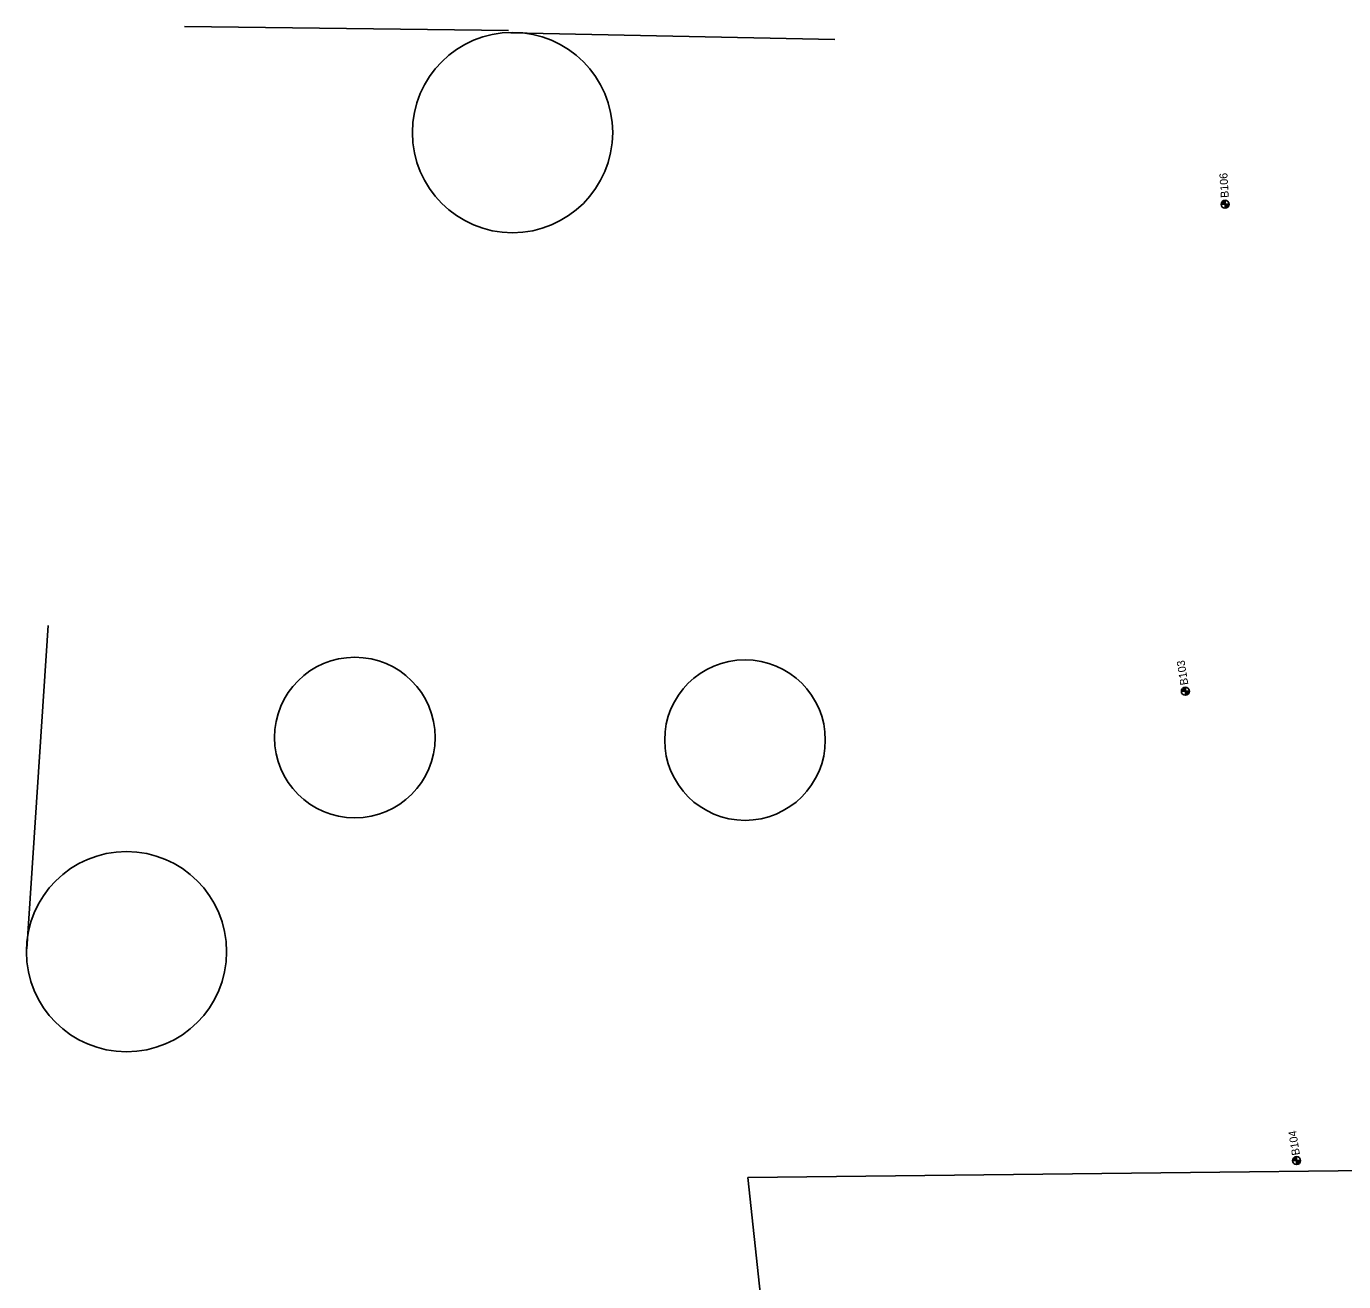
# Model space of a CAD drawing. Extents: x 311409 to 379449, y 121539 to 224848.
# Drawn here: x 354135 to 355782, y 184658 to 186227 of the extents above; entities that cross this region are included whole.
import ezdxf

# ---------------------------------------------------------------- set-up
doc = ezdxf.new("R2010")
doc.units = 0
for name, color, linetype in [('CE-TOPO-CONC-SLAB', 7, 'Continuous'), ('E_SOIL_BORE1 [KAPUR_CADDS_LEVELS]', 7, 'Continuous'), ('E_SOIL_BORE2 [KAPUR_CADDS_LEVELS]', 7, 'Continuous'), ('P_MARK', 7, 'Continuous'), ('P_TC', 7, 'Continuous'), ('SIGNS-POLES', 7, 'Continuous')]:
    doc.layers.add(name, color=color, linetype=linetype)

msp = doc.modelspace()

# ---------------------------------------------------------------- linework, layer by layer
at = {"layer": 'CE-TOPO-CONC-SLAB'}
for centre in [(354545.6, 185338.2), (355033.3, 185335.1)]:
    msp.add_circle(centre, 100.4, dxfattribs=at)
at = {"layer": 'P_MARK'}
for p, q in [((355628.3, 186004.9), (355638.3, 186004.9)), ((355633.3, 186009.9), (355633.3, 185999.9)), ((355578.7, 185396.1), (355588.7, 185396.1)), ((355583.7, 185401.1), (355583.7, 185391.1)), ((355722.7, 184814.3), (355722.7, 184804.3)), ((355717.7, 184809.3), (355727.7, 184809.3))]:
    msp.add_line(p, q, dxfattribs=at)
for centre in [(355633.3, 186004.9), (355583.7, 185396.1), (355722.7, 184809.3)]:
    msp.add_circle(centre, 5, dxfattribs=at)
for centre, radius, start, end in [((355633.3, 186004.9), 4.5, 89.9869, 179.9869), ((355633.3, 186004.9), 4, 89.9869, 179.9869), ((355633.3, 186004.9), 3.5, 89.9869, 179.9869), ((355633.3, 186004.9), 3, 89.9869, 179.9869), ((355633.3, 186004.9), 2.5, 89.9869, 179.9869), ((355633.3, 186004.9), 2, 89.9869, 179.9869), ((355633.3, 186004.9), 1.5, 89.9869, 179.9869), ((355633.3, 186004.9), 1, 89.9869, 179.9869), ((355633.3, 186004.9), 0.5, 89.9869, 179.9869), ((355633.3, 186004.9), 4.5, 269.9869, 359.9869), ((355633.3, 186004.9), 4, 269.9869, 359.9869), ((355633.3, 186004.9), 3.5, 269.9869, 359.9869), ((355633.3, 186004.9), 3, 269.9869, 359.9869), ((355633.3, 186004.9), 2.5, 269.9869, 359.9869), ((355633.3, 186004.9), 2, 269.9869, 359.9869), ((355633.3, 186004.9), 1.5, 269.9869, 359.9869), ((355633.3, 186004.9), 1, 269.9869, 359.9869), ((355633.3, 186004.9), 0.5, 269.9869, 359.9869), ((355583.7, 185396.1), 4.5, 89.9869, 179.9869), ((355583.7, 185396.1), 4, 89.9869, 179.9869), ((355583.7, 185396.1), 3.5, 89.9869, 179.9869), ((355583.7, 185396.1), 3, 89.9869, 179.9869), ((355583.7, 185396.1), 2.5, 89.9869, 179.9869), ((355583.7, 185396.1), 2, 89.9869, 179.9869), ((355583.7, 185396.1), 1.5, 89.9869, 179.9869), ((355583.7, 185396.1), 1, 89.9869, 179.9869), ((355583.7, 185396.1), 0.5, 89.9869, 179.9869), ((355583.7, 185396.1), 4.5, 269.9869, 359.9869), ((355583.7, 185396.1), 4, 269.9869, 359.9869), ((355583.7, 185396.1), 3.5, 269.9869, 359.9869), ((355583.7, 185396.1), 3, 269.9869, 359.9869), ((355583.7, 185396.1), 2.5, 269.9869, 359.9869), ((355583.7, 185396.1), 2, 269.9869, 359.9869), ((355583.7, 185396.1), 1.5, 269.9869, 359.9869), ((355583.7, 185396.1), 1, 269.9869, 359.9869), ((355583.7, 185396.1), 0.5, 269.9869, 359.9869), ((355722.7, 184809.3), 4.5, 89.9869, 179.9869), ((355722.7, 184809.3), 4, 89.9869, 179.9869), ((355722.7, 184809.3), 3.5, 89.9869, 179.9869), ((355722.7, 184809.3), 3, 89.9869, 179.9869), ((355722.7, 184809.3), 2.5, 89.9869, 179.9869), ((355722.7, 184809.3), 2, 89.9869, 179.9869), ((355722.7, 184809.3), 1.5, 89.9869, 179.9869), ((355722.7, 184809.3), 1, 89.9869, 179.9869), ((355722.7, 184809.3), 0.5, 89.9869, 179.9869), ((355722.7, 184809.3), 4.5, 269.9869, 359.9869), ((355722.7, 184809.3), 4, 269.9869, 359.9869), ((355722.7, 184809.3), 3.5, 269.9869, 359.9869), ((355722.7, 184809.3), 3, 269.9869, 359.9869), ((355722.7, 184809.3), 2.5, 269.9869, 359.9869), ((355722.7, 184809.3), 2, 269.9869, 359.9869), ((355722.7, 184809.3), 1.5, 269.9869, 359.9869), ((355722.7, 184809.3), 1, 269.9869, 359.9869), ((355722.7, 184809.3), 0.5, 269.9869, 359.9869)]:
    msp.add_arc(centre, radius, start, end, dxfattribs=at)
at = {"layer": 'P_TC'}
msp.add_lwpolyline([(356823.5, 180783.3), (356761.3, 181116.1), (356759.2, 181127.3), (356364.8, 184803), (355036.9, 184788), (355432.6, 181099.4), (355498.3, 180748.1)], dxfattribs=at)
at = {"layer": 'SIGNS-POLES'}
for p, q in [((354332.7, 186227.4), (354737.7, 186222.3)), ((354740.6, 186219.2), (355145.5, 186211)), ((354135.6, 185074), (354162.2, 185478.2))]:
    msp.add_line(p, q, dxfattribs=at)
for centre in [(354742.7, 186094.6), (354260.2, 185070.5)]:
    msp.add_circle(centre, 125.2, dxfattribs=at)

# ---------------------------------------------------------------- texts
at = {"layer": 'E_SOIL_BORE1 [KAPUR_CADDS_LEVELS]'}
msp.add_text('B104', height=10, rotation=98.957, dxfattribs=at).set_placement((355727, 184816.6))
at = {"layer": 'E_SOIL_BORE2 [KAPUR_CADDS_LEVELS]'}
for s, rotation, p in [('B106', 93.5868, (355638.1, 186013.3)), ('B103', 98.957, (355587.5, 185404.5))]:
    msp.add_text(s, height=10, rotation=rotation, dxfattribs=at).set_placement(p)

doc.saveas('drawing.dxf')
